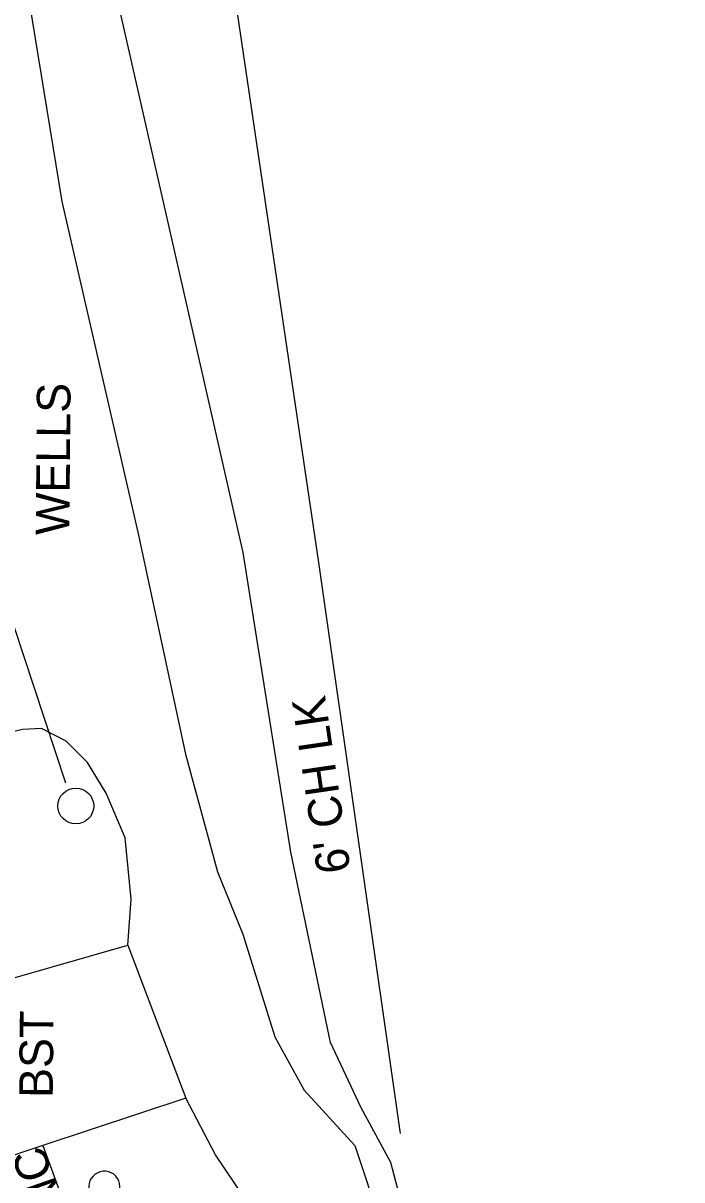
# Model space of a CAD drawing. Extents: x 945964 to 948456, y 631061 to 636061.
# Drawn here: x 946602.4 to 946680.8, y 633061.9 to 633199.7 of the extents above; entities that cross this region are included whole.
import ezdxf

# ---------------------------------------------------------------- set-up
doc = ezdxf.new("R2010")
doc.units = 0
for name, color, linetype in [('Exist Other Culture Fence Line', 7, 'Continuous'), ('Exist Other Culture Fence Line Text', 7, 'Continuous'), ('Exist Other Culture Well CELL', 7, 'Continuous'), ('Exist Other Culture Well Leader', 7, 'Continuous'), ('Exist Other Culture Well Text', 7, 'Continuous'), ('Exist Roads EOP Other', 7, 'Continuous'), ('Exist Roads EOP Other Text', 7, 'Continuous'), ('Exist Roads Soil', 7, 'Continuous'), ('Exist Vegetation Tree CELL', 7, 'Continuous'), ('Exist Vegetation Woods Line', 7, 'Continuous')]:
    doc.layers.add(name, color=color, linetype=linetype)

# ---------------------------------------------------------------- blocks, each defined once
blk = doc.blocks.new('EXIST OTHER CULTURE WELL')
at = {"layer": 'Exist Other Culture Well CELL'}
blk.add_circle((0.0001, 0.0001), 0.0512, dxfattribs=at)
blk = doc.blocks.new('EXIST VEGETATION TREE')
at = {"layer": 'Exist Vegetation Tree CELL'}
blk.add_line((0, 0), (0, 0), dxfattribs=at)
blk.add_circle((0, 0), 0.00652, dxfattribs=at)
for centre, radius, start, end in [((-0.0077, 0.0575), 0.0371, 330.1651, 219.7134), ((-0.0521, 0.0031), 0.0345, 62.6636, 279.3457), ((0.051, 0.0118), 0.038, 257.1011, 134.1999), ((0.0335, -0.058), 0.034, 181.2822, 74.56), ((-0.0341, -0.0624), 0.0338, 111.5671, 6.231)]:
    blk.add_arc(centre, radius, start, end, dxfattribs=at)

msp = doc.modelspace()

# ---------------------------------------------------------------- linework, layer by layer
at = {"layer": 'Exist Other Culture Fence Line'}
msp.add_lwpolyline([(946591.85, 633445.71), (946616.31, 633279.08), (946637.55, 633135.48), (946647.25, 633067.46)], dxfattribs=at)
at = {"layer": 'Exist Other Culture Well Leader'}
msp.add_lwpolyline([(946607.44, 633109.21), (946601.22, 633128.08)], dxfattribs=at)
at = {"layer": 'Exist Roads EOP Other'}
for points in [[(946591.7, 633083.26), (946614.82, 633089.88), (946621.73, 633071.67), (946604.7, 633066.02)], [(946604.7, 633066.02), (946598.64, 633064.01)], [(946604.7, 633066.02), (946610.51, 633050.17)]]:
    msp.add_lwpolyline(points, dxfattribs=at)
at = {"layer": 'Exist Roads Soil'}
for points in [[(946614.82, 633089.88), (946615.22, 633095.38), (946614.52, 633102.68), (946612.25, 633108), (946610.03, 633111.67), (946607.48, 633114.18), (946604.55, 633115.71), (946602.28, 633115.59), (946599.94, 633115.05), (946595.37, 633114), (946588.61, 633132.12), (946582.89, 633149.76), (946578.1, 633168.29), (946578.56, 633171.42), (946573.24, 633187.37), (946569.13, 633199.35), (946567.17, 633207.19)], [(946602.39, 633206.69), (946606.99, 633178.5), (946616.01, 633139.1), (946621.7, 633112.67), (946625.52, 633098.62), (946628.54, 633091.21), (946632.32, 633078.98), (946635.84, 633072.6), (946641.86, 633066.02), (946644.95, 633056.7), (946645.93, 633052.62), (946633.86, 633049.06), (946630.77, 633056.74), (946625.26, 633064.9), (946621.73, 633071.67)]]:
    msp.add_lwpolyline(points, dxfattribs=at)
at = {"layer": 'Exist Vegetation Woods Line'}
msp.add_lwpolyline([(946680.79, 632991.8), (946667.29, 632956.38), (946657.39, 632943.45), (946652.06, 632943.64), (946645.33, 632951.91), (946642.52, 632962.46), (946642.83, 632973.87), (946646.81, 632988.75), (946648.29, 633000.71), (946649.63, 633008.71), (946650.21, 633022.42), (946650.47, 633036.4), (946648.76, 633054.02), (946646.15, 633063.99), (946642.6, 633070.53), (946638.95, 633078.29), (946634.26, 633100.99), (946628.55, 633136.66), (946613.13, 633204.65)], dxfattribs=at)

# ---------------------------------------------------------------- block references
at = {"layer": 'Exist Other Culture Well CELL', "xscale": 41.66666666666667, "yscale": 41.66666666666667}
msp.add_blockref('EXIST OTHER CULTURE WELL', (946608.64, 633106.47), dxfattribs=at)
at = {"layer": 'Exist Vegetation Tree CELL', "xscale": 50, "yscale": 50}
msp.add_blockref('EXIST VEGETATION TREE', (946612.43, 633058.23), dxfattribs=at)

# ---------------------------------------------------------------- texts
at = {"layer": 'Exist Other Culture Fence Line Text'}
msp.add_text("6' CH LK", height=4, rotation=98.3521, dxfattribs=at).set_placement((946641.38, 633098.75))
at = {"layer": 'Exist Other Culture Well Text'}
msp.add_text('WELLS', height=4, rotation=89.5187, dxfattribs=at).set_placement((946607.87, 633138.74))
at = {"layer": 'Exist Roads EOP Other Text'}
for s, rotation, p in [('BST', 89.5187, (946605.9, 633071.68)), ('CONC', 109.1921, (946609.9, 633051.34))]:
    msp.add_text(s, height=4, rotation=rotation, dxfattribs=at).set_placement(p)

doc.saveas('drawing.dxf')
